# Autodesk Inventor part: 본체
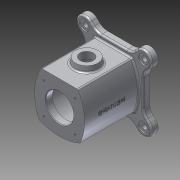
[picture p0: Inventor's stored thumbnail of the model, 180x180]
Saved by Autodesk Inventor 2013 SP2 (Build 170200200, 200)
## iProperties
Created: 2022-01
Part Number: 본체
Material: 알루미늄 6061
Document SubType Name: Modeling
Designer: a
Density: 2.71 g/cm^3
Mass: 1230.9 g
Surface Area: 908.329 cm^2
Volume: 454.205 cm^3
Author: a
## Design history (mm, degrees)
sketch "스케치1"
  geometry: L1 (-45, 45)-(45, 45); L2 (45, 45)-(45, -45); L3 (45, -45)-(-45, -45); L4 (-45, -45)-(-45, 45); 3 further points
  constraints: 8 end point, 2 midpoint, 2 parallel, 1 horizontal, 1 horizontal alignment, 1 perpendicular, 1 vertical alignment
  dimensions: "d0" = 90 distance of L1.end L2.end; "d2" = 90 distance of L1.start L1.end
extrude "돌출1" new body sketch "스케치1" stored distance "d3" = 110; taper "d4" = 0 deg
sketch "스케치2"
  geometry: L1 (45, -55)-(-45, -55) reference; L2 (-45, -55)-(-45, 55) reference; L3 (-45, 55)-(45, 55) reference; L4 (45, 55)-(45, -55) reference; L5 (25, 55)-(25, 43); L6 (25, 43)-(37, 43); L7 (37, 43)-(37, -43); L8 (37, -43)-(25, -43); L9 (25, -43)-(25, -55); L10 (0, 55)-(0, -55); 1 further point
  constraints: 12 end point, 3 parallel, 2 midpoint, 2 perpendicular, 2 point on line
  dimensions: "d5" = 12 distance of L5.start L5.end; "d7" = 86 distance of L6.end L7.end; "d8" = 50 diameter of L5 L10; "d9" = 74 diameter of L7 L10; "d10" = 50 diameter of L9 L10
revolve "회전1" sketch "스케치2" stored, may be unused: angle "d11" = 90 deg
fillet "모깎기1" dims "d12" = 3
node "작업 평면1"
sketch "스케치3"
  geometry: L1 (45, -55)-(-45, -55) reference; C1 r 20 at (0, 6); 1 further point
  constraints: 1 centre point, 1 vertical alignment
  dimensions: "d14" = 40 diameter of C1; "d15" = 61 distance from line of C1.centre L1
extrude "돌출2" join sketch "스케치3" stored distance "d16" = 110; taper "d17" = 10 deg
sketch "스케치4"
  geometry: C1 r 20 at (0, 0) reference; C2 r 12 at (0, 0); 1 further point
  constraints: 1 centre point, 1 coincident
  dimensions: "d18" = 24 diameter of C2
extrude "돌출3" cut sketch "스케치4" distance "d19" = 13; taper "d20" = 0 deg
sketch "스케치5"
  geometry: C1 r 12 at (0, 0) reference; C2 r 15 at (0, 0); 1 further point
  constraints: 1 centre point, 1 coincident
  dimensions: "d21" = 30 diameter of C2
extrude "돌출4" cut sketch "스케치5" stored distance "d22" = 13; taper "d23" = 0 deg
chamfer "모따기1" distance "d24" = 1; stored, may be unused: second distance "d25" = 2, angle "d26" = 45 deg
chamfer "모따기2" distance "d27" = 1; stored, may be unused: second distance "d28" = 2, angle "d29" = 45 deg
sketch "스케치6"
  geometry: L1 (45, 45)-(-45, 45) reference; L2 (-45, 45)-(-45, -45) reference; L3 (-45, -45)-(45, -45) reference; L4 (45, -45)-(45, 45) reference; A1 r 90 centre (-45, 0) between (32.942, -45) and (32.942, 45)
  constraints: 2 point on circle, 2 point on line, 1 centre point, 1 midpoint
  dimensions: "d31" = 180 diameter of A1
extrude "돌출5" cut sketch "스케치6" stored distance "d32" = 13; taper "d33" = 0 deg
sketch "스케치7"
  geometry: L1 (-32.942, -45)-(45, -45) reference; L2 (45, -45)-(45, 45) reference; L3 (45, 45)-(-32.942, 45) reference; A1 r 90 centre (45, 0) between (-32.942, 45) and (-32.942, -45) reference; A2 r 90 centre (-45, 0) between (32.942, -45) and (32.942, 45)
  constraints: 3 point on circle, 2 point on line, 1 centre point
  dimensions: "d34" = 180 diameter of A2
extrude "돌출6" cut sketch "스케치7" stored distance "d35" = 13; taper "d36" = 0 deg
sketch "스케치8"
  geometry: L1 (32.942, 45)-(-32.942, 45) reference; L2 (-32.942, -45)-(32.942, -45) reference; A1 r 90 centre (-45, 0) between (32.942, -45) and (32.942, 45) reference; A2 r 90 centre (45, 0) between (-32.942, 45) and (-32.942, -45) reference; A3 r 90 centre (0, 45) between (-37.029, -37.029) and (37.029, -37.029)
  constraints: 4 point on circle, 1 centre point, 1 midpoint
  dimensions: "d37" = 180 diameter of A3
extrude "돌출7" cut sketch "스케치8" stored distance "d38" = 0; taper "d39" = 0 deg
sketch "스케치9"
  geometry: L1 (32.942, 45)-(-32.942, 45) reference; L2 (-53, 53)-(53, 53); L3 (53, 53)-(53, -53); L4 (53, -53)-(-53, -53); L5 (-53, -53)-(-53, 53); C1 r 26 at (0, 0) reference; A1 r 90 centre (0, 45) between (-37.029, -37.029) and (37.029, -37.029) reference; A2 r 90 centre (-45, 0) between (37.029, -37.029) and (32.942, 45) reference; A3 r 90 centre (45, 0) between (-32.942, 45) and (-37.029, -37.029) reference; 2 further points
  constraints: 8 end point, 2 midpoint, 2 parallel, 1 horizontal, 1 horizontal alignment, 1 perpendicular, 1 vertical alignment
  dimensions: "d40" = 106 distance of L2.start L2.end; "d42" = 106 distance of L4.end L2.start
extrude "돌출8" join sketch "스케치9" distance "d43" = 12; taper "d44" = 0 deg
sketch "스케치11"
  geometry: L1 (0, 0)-(-28.284, 28.284); L2 (0, 0)-(40, 0); C1 r 26 at (0, 0) reference; C2 r 40 at (0, 0); 1 further point
  constraints: 4 end point, 2 coincident, 1 centre point, 1 equal length, 1 horizontal
  dimensions: "d48" = 80 diameter of C2; "d49" = 40 distance of L1.start L1.end; "d50" = 135 deg angle of L2 L1
hole "구멍1" sketch "스케치11" at (-28.284, 28.284) diameter "d51" = 3.242; stored, may be unused: countersink angle "d55" = 90 deg, drill point angle "d57" = 118 deg; dims "d52" = 9, "d53" = 4, "d54" = 2, "d56" = 11
sketch "스케치12"
  geometry: L1 (0, 0)-(-28.284, 28.284); L2 (0, 0)-(40, 0); C1 r 26 at (0, 0) reference; 1 further point
  constraints: 4 end point, 1 coincident, 1 equal length, 1 horizontal
  dimensions: "d61" = 40 distance of L1.start L1.end; "d62" = 135 deg angle of L2 L1
hole "구멍2" sketch "스케치12" at (-28.284, 28.284) diameter "d63" = 3.242; stored, may be unused: countersink angle "d67" = 90 deg, drill point angle "d69" = 118 deg; dims "d64" = 9, "d65" = 4, "d66" = 2, "d68" = 11
fillet "모깎기2" dims "d73" = 3
fillet "모깎기3" dims "d74" = 3
fillet "모깎기4" dims "d75" = 3
node "작업 평면2"
sketch "스케치13"
  geometry: L1 (-53, -55)-(53, -55) reference; L2 (55, 26)-(55, -14) reference; 2 further points
  constraints: 1 other
  dimensions: "d77" = 61 distance from line of L1 point (0, 6); "d78" = 55 distance from line of L2 point (0, 6)
feature "엠보싱1" sketch "스케치13" dims "d0" = 90, "d2" = 90, "d79" = 0.5, "d80" = 0
sketch "스케치14"
  geometry: L1 (42.393, 63.607)-(63.607, 42.393); L2 (42.393, 63.607)-(72.393, 63.607); L3 (42.393, 63.607)-(63.607, 42.393); L4 (63.607, 42.393)-(42.849, 21.635); L5 (42.849, 21.635)-(21.635, 42.849); L6 (21.635, 42.849)-(42.393, 63.607); C1 r 26 at (0, 0) reference; C2 r 75 at (0, 0); C3 r 15 at (53, 53); 2 further points
  constraints: 12 end point, 4 equal length, 2 centre point, 2 coincident, 2 midpoint, 1 horizontal, 1 perpendicular
  dimensions: "d81" = 150 diameter of C2; "d90" = 30 diameter of C3; "d91" = 30 distance of L1.start L1.end; "d92" = 45 deg angle of L1 L2; "d93" = 29.35619 distance from line of L5 point (53, 53)
extrude "돌출9" join sketch "스케치14" distance "d94" = 12; taper "d95" = 0 deg
fillet "모깎기5" dims "d106" = 20
fillet "모깎기6" dims "d107" = 3
sketch "스케치16"
  geometry: L1 (39.766, 56.737)-(44.515, 61.485) reference; L2 (0, 0)-(-53.033, 53.033); L3 (0, 0)-(75, 0); 1 further point
  constraints: 4 end point, 1 coincident, 1 equal length, 1 horizontal, 1 perpendicular
  dimensions: "d108" = 75 distance of L2.start L2.end; "d109" = 135 deg angle of L3 L2 (derived)
hole "구멍4" sketch "스케치16" at (-53.033, 53.033) diameter "d110" = 9; stored, may be unused: countersink angle "d114" = 90 deg, drill point angle "d116" = 118 deg; dims "d111" = 9, "d112" = 18, "d113" = 2, "d115" = 11
node "솔리드1"
pattern_circular "원형 패턴1" dims angle "d59" = 360 deg
pattern_circular "원형 패턴2" dims angle "d71" = 360 deg
pattern_circular "원형 패턴3" dims angle "d104" = 360 deg
pattern_circular "원형 패턴4" dims angle "d118" = 360 deg
node "절단 모서리 투영1"
other parameters: "d13" = 55, "d47" = 15, "d83" = 15, "d84" = 15
